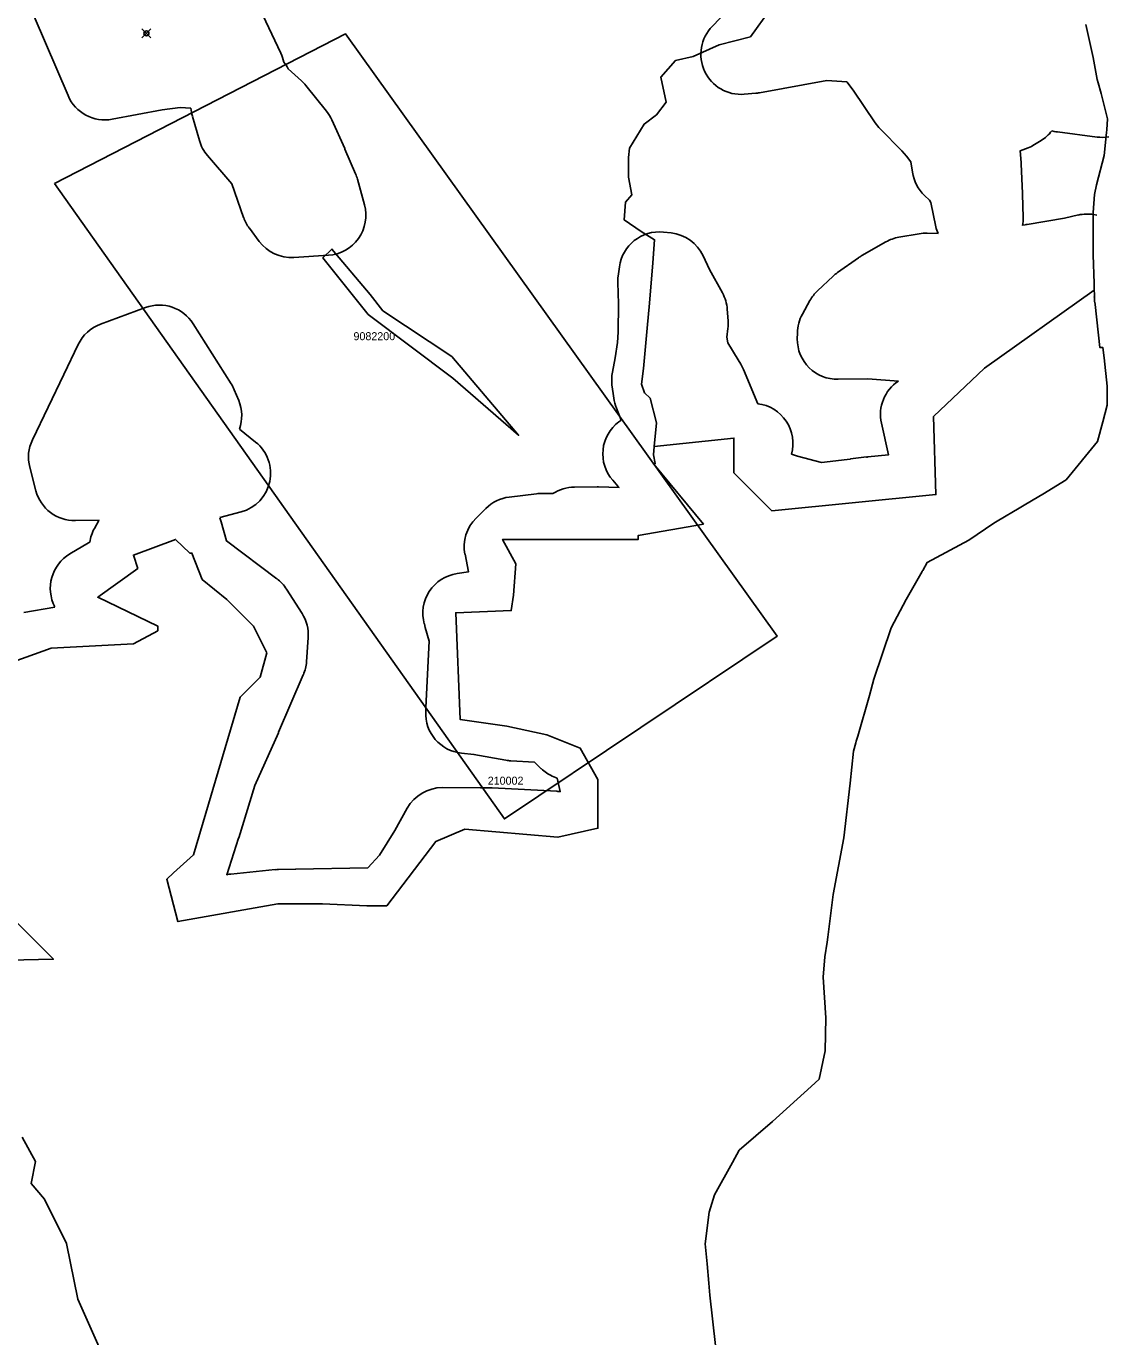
# Model space of a CAD drawing. Extents: x -546762 to -536351, y -1046851 to -1035695.
# Drawn here: x -541589 to -540237, y -1040804 to -1039166 of the extents above; entities that cross this region are included whole.
import ezdxf

# ---------------------------------------------------------------- set-up
doc = ezdxf.new("R2010")
doc.units = 0
for name, color, linetype in [('Vrstva 23', 7, 'Continuous'), ('Vrstva 24', 7, 'Continuous'), ('Vrstva 43', 7, 'Continuous'), ('Vrstva 46', 7, 'Continuous'), ('Vrstva 49', 7, 'Continuous')]:
    doc.layers.add(name, color=color, linetype=linetype)

msp = doc.modelspace()

# ---------------------------------------------------------------- linework, layer by layer
at = {"layer": 'Vrstva 23'}
for points in [[(-540687, -1039021.4), (-540674.7, -1039016.8), (-540651.8, -1039025.4), (-540649.4, -1039037.7), (-540668.5, -1039076.7), (-540699, -1039130.7), (-540722.5, -1039156.4), (-540732, -1039166)], [(-541271.1, -1039199.7), (-541316, -1039104.2)], [(-541579.2, -1039153.9), (-541536.9, -1039252.8)], [(-541245.2, -1039234.4), (-541262, -1039219.2)], [(-541214, -1039272.4), (-541239.9, -1039240.2)], [(-540673.2, -1039249.2), (-540588.9, -1039234), (-540564.1, -1039235.7), (-540556.2, -1039246), (-540528.6, -1039286.9)], [(-540692.2, -1039251), (-540677.9, -1039249.8)], [(-541481.7, -1039282.3), (-541419.5, -1039270.7), (-541397, -1039267.7), (-541383.5, -1039268.3)], [(-541381.6, -1039278.7), (-541372.8, -1039309)], [(-541191.3, -1039319), (-541207.4, -1039283.2)], [(-540522.6, -1039294.1), (-540495.3, -1039321.6), (-540489.4, -1039328.3), (-540484, -1039335.5), (-540482.1, -1039348.6)], [(-540308.1, -1039296.9), (-540304.9, -1039297.5)], [(-540329.7, -1039314), (-540321.5, -1039308.9)], [(-540301.1, -1039298.2), (-540251.5, -1039304.6)], [(-541362.8, -1039327.6), (-541332.3, -1039363.2), (-541317.5, -1039405.3)], [(-541177.7, -1039350.6), (-541191, -1039319.7)], [(-540346.4, -1039336.4), (-540347.6, -1039321.9), (-540337.7, -1039318)], [(-540344.6, -1039375.2), (-540346.3, -1039338.1)], [(-541166.6, -1039389.2), (-541175.4, -1039357.1)], [(-540466.9, -1039377.5), (-540460.8, -1039383.3), (-540459.3, -1039386.4), (-540452.8, -1039416.7)], [(-540343.8, -1039405.2), (-540344.6, -1039376.1)], [(-540274.8, -1039402), (-540292.2, -1039406), (-540338.9, -1039413.8)], [(-540251.8, -1039402.1), (-540255.4, -1039401.5)], [(-541310.4, -1039418.5), (-541298.2, -1039435)], [(-540783.6, -1039424.5), (-540793.2, -1039423.5)], [(-540473.8, -1039425.5), (-540498.9, -1039429.8)], [(-540450.1, -1039425.3), (-540463.8, -1039424.8)], [(-540341.1, -1039414.2), (-540344.5, -1039414.9)], [(-540515.2, -1039435.6), (-540545.4, -1039452.8)], [(-541254.8, -1039455.1), (-541211.6, -1039452.3)], [(-540719.5, -1039499.4), (-540735.7, -1039470.3), (-540743.7, -1039453.1)], [(-540549.6, -1039455.4), (-540575.7, -1039473.8)], [(-540848.2, -1039466.8), (-540849.6, -1039478.5)], [(-540850, -1039486.5), (-540849.1, -1039513.2), (-540849.5, -1039548.5), (-540850.4, -1039561.4), (-540853.5, -1039580.4), (-540856.9, -1039598.6)], [(-540581.1, -1039478.3), (-540600.7, -1039496.8)], [(-540610.1, -1039508.9), (-540619.5, -1039525.9)], [(-541440.1, -1039517.8), (-541496.4, -1039538.6)], [(-540712.3, -1039534.1), (-540713.4, -1039519.9)], [(-541333.1, -1039613), (-541380.6, -1039538)], [(-540699.9, -1039583), (-540712.9, -1039561.7), (-540713.8, -1039554.6), (-540712.5, -1039543.9)], [(-540625.8, -1039549.6), (-540625.9, -1039556.9)], [(-541524.2, -1039563.8), (-541542.2, -1039601.4), (-541542.2, -1039601.4), (-541581.4, -1039683)], [(-540696.6, -1039588.4), (-540699.9, -1039583.1)], [(-540675.4, -1039637.9), (-540693.1, -1039595.3)], [(-540575, -1039607.4), (-540538, -1039606.7), (-540499.5, -1039609.6)], [(-541323.7, -1039633.8), (-541329.2, -1039620.6)], [(-540857.4, -1039614.2), (-540856, -1039625.2)], [(-540856, -1039625.2), (-540855.2, -1039630.9)], [(-540851.9, -1039643.4), (-540845.9, -1039658.3)], [(-541302.6, -1039685.8), (-541322.8, -1039669.6)], [(-540846.3, -1039658.7), (-540848.9, -1039660.6)], [(-540520.9, -1039662.1), (-540512.2, -1039701.9), (-540537.9, -1039704.4)], [(-540559.8, -1039707.1), (-540563.5, -1039707.6), (-540595.5, -1039711.3), (-540625.8, -1039703.6), (-540633.3, -1039701)], [(-540539.3, -1039704.5), (-540559.4, -1039707)], [(-541584.6, -1039717.3), (-541576.9, -1039746.7)], [(-540856.5, -1039733.6), (-540850.1, -1039740.9)], [(-540951.6, -1039750.4), (-540985.8, -1039754.6)], [(-540931.2, -1039750.1), (-540945.1, -1039750)], [(-540875.8, -1039741.9), (-540904.3, -1039742.1)], [(-540849.6, -1039741.5), (-540848.6, -1039742.6), (-540874.1, -1039741.9)], [(-541347.3, -1039780.3), (-541320.7, -1039773.1)], [(-541014.9, -1039768.7), (-541027.2, -1039780.8)], [(-541527.6, -1039784), (-541498.2, -1039783.5)], [(-541498.5, -1039784), (-541503.9, -1039793.7)], [(-541276, -1039856.6), (-541338.8, -1039809.3), (-541345.6, -1039785.5)], [(-541511.3, -1039811.9), (-541534.5, -1039825.7)], [(-541041, -1039826.1), (-541036.7, -1039848.1), (-541050.9, -1039850.2)], [(-541244.6, -1039900), (-541263.9, -1039869.7)], [(-541553.3, -1039892), (-541591.9, -1039898.9)], [(-541091.8, -1039913.1), (-541090.6, -1039917.5), (-541085.9, -1039934.7), (-541089.9, -1040017.8)], [(-541239.1, -1039960.4), (-541237, -1039930.3)], [(-541273.8, -1040048.5), (-541243, -1039976.6)], [(-541089.9, -1040017.8), (-541090.1, -1040022.7)], [(-541323.7, -1040180.4), (-541303.5, -1040115.1), (-541274.1, -1040049.2)], [(-541045.2, -1040074.8), (-541029.9, -1040076.3), (-540989.9, -1040083.5)], [(-540983.7, -1040084.2), (-540954.3, -1040085.8), (-540945.7, -1040094.1)], [(-540932.1, -1040103.3), (-540925.9, -1040106.1), (-540922, -1040122.7), (-540923.6, -1040122.6)], [(-541009.5, -1040117.9), (-541021.7, -1040117.9), (-541069.3, -1040117.8)], [(-540926.3, -1040122.4), (-541007, -1040118)], [(-541113.1, -1040143.4), (-541128.8, -1040171.5), (-541147.8, -1040202.2), (-541162.3, -1040218), (-541252.6, -1040219.7)], [(-541337.6, -1040226.4), (-541338.7, -1040226.6), (-541323.9, -1040181)], [(-541278.2, -1040220.3), (-541333.7, -1040225.8)], [(-541252.6, -1040219.7), (-541274.2, -1040220.1)]]:
    msp.add_lwpolyline(points, dxfattribs=at)
for centre, start, end in [((-540696.4, -1039201.2), 135.2787, 274.7968), ((-541316.4, -1039221), 11.6578, 25.1714), ((-541306.5, -1039242.1), 27.3262, 38.687), ((-541278.9, -1039271.4), 38.7334, 47.7618), ((-541490.9, -1039233.1), 203.1566, 280.5586), ((-540682.1, -1039200), 274.7968, 280.2491), ((-541333.6, -1039264.7), 184.1005, 196.1993), ((-541253, -1039303.7), 24.2144, 38.7334), ((-540487.1, -1039258.9), 214.0406, 224.7993), ((-540347.7, -1039266.4), 301.6423, 322.4121), ((-540294.7, -1039248.6), 258.2417, 262.6546), ((-541324.8, -1039295.1), 196.1993, 220.5926), ((-540355.9, -1039271.5), 291.4062, 301.6423), ((-540245.1, -1039255), 262.6546, 279.5263), ((-541236.9, -1039339.5), 23.2769, 24.2144), ((-540396.3, -1039340.4), 2.6117, 4.5691), ((-541223.6, -1039370.3), 15.3684, 23.2769), ((-540432.6, -1039341.2), 188.5527, 226.6352), ((-540394.6, -1039377.5), 1.5561, 2.6117), ((-541214.8, -1039402.4), 273.6531, 15.3684), ((-541270.3, -1039388.7), 199.3971, 216.6026), ((-540393.8, -1039406.6), 350.4057, 1.5561), ((-540263.7, -1039450.8), 80.4998, 102.7951), ((-540798.6, -1039473.2), 83.7978, 172.7477), ((-540789, -1039474.2), 24.9468, 83.7978), ((-540465.4, -1039474.8), 88.2017, 99.7174), ((-540403.9, -1039406.2), 192.1517, 202.4009), ((-540330.7, -1039463.1), 99.445, 101.9338), ((-541258, -1039405.2), 216.6026, 273.6531), ((-540490.5, -1039479.1), 99.7174, 119.5569), ((-540520.8, -1039496.3), 119.5569, 125.2703), ((-540546.8, -1039514.7), 125.2703, 133.3763), ((-540800.1, -1039484.8), 172.7477, 181.9352), ((-540763.2, -1039523.7), 4.2841, 29.0498), ((-540566.4, -1039533.2), 133.3763, 150.9711), ((-541422.8, -1039564.7), 32.3202, 110.2362), ((-540575.8, -1039550.2), 150.9711, 179.366), ((-541479.1, -1039585.5), 110.2362, 154.352), ((-540762.2, -1039537.8), 353.0657, 4.2841), ((-540575.9, -1039557.4), 179.366, 271.0512), ((-540742.5, -1039609.1), 31.373, 31.4212), ((-540739.3, -1039614.4), 22.5577, 31.373), ((-540807.8, -1039607.9), 169.294, 187.2663), ((-541375.4, -1039639.7), 22.45, 32.3202), ((-540806.4, -1039618.9), 187.2663, 187.3108), ((-540472.1, -1039651.4), 123.2647, 192.4075), ((-541369.9, -1039652.9), 340.4575, 22.45), ((-540805.6, -1039624.5), 187.3108, 202.159), ((-540681.4, -1039687.5), 344.3403, 83.0992), ((-540816.4, -1039698.7), 126.1246, 126.7976), ((-540818.9, -1039700.6), 126.7976, 221.314), ((-541536.3, -1039704.6), 154.3549, 194.6946), ((-541333.8, -1039724.9), 285.1759, 51.3277), ((-540553.2, -1039756.6), 97.1004, 97.5856), ((-540533.1, -1039754.2), 95.5519, 97.1004), ((-541528.6, -1039734), 194.6946, 271.0698), ((-540979.7, -1039804.2), 97.0508, 134.7185), ((-540945.5, -1039800), 89.4765, 97.0508), ((-540904, -1039792.1), 90.4009, 122.9834), ((-540875.4, -1039791.9), 88.4792, 90.4009), ((-540812.6, -1039707.9), 221.314, 222.2515), ((-541454.8, -1039808.4), 150.1205, 150.7815), ((-541393.7, -1039799.2), 15.8145, 22.1185), ((-540992, -1039816.4), 134.7185, 191.2035), ((-541460.3, -1039818.1), 150.7815, 171.8664), ((-541485.8, -1039854.9), 118.7077, 120.6621), ((-541509, -1039868.7), 120.6621, 207.698), ((-541043.7, -1039899.7), 98.3818, 195.557), ((-541306.1, -1039896.5), 32.3928, 53.0281), ((-541286.8, -1039926.8), 355.9822, 32.3928), ((-541288.9, -1039956.9), 336.7947, 355.9822), ((-541039.9, -1040020.2), 177.2255, 177.2737), ((-541040.2, -1040025), 177.2737, 264.2072), ((-541319.8, -1040028.8), 335.9562, 336.7947), ((-540981.1, -1040034.3), 259.8374, 266.9551), ((-540911.2, -1040057.9), 226.3449, 245.2107), ((-541069.4, -1040167.8), 89.8555, 150.8568), ((-541009.7, -1040167.9), 86.9216, 89.8589), ((-540929, -1040172.3), 83.7774, 86.9216), ((-541371.5, -1040165.6), 342.0457, 342.7969), ((-541328.8, -1040275.6), 95.6482, 100.1404), ((-541273.2, -1040270.1), 91.0874, 95.6482), ((-541251.6, -1040269.7), 91.0752, 91.0874)]:
    msp.add_arc(centre, 50, start, end, dxfattribs=at)
at = {"layer": 'Vrstva 24'}
for points in [[(-540659.7, -1039145.3), (-540684.5, -1039179.1), (-540723.5, -1039189.5), (-540756.1, -1039203.8), (-540778.2, -1039209), (-540796.4, -1039229.9), (-540789.9, -1039261.1), (-540801.6, -1039276.7), (-540817.2, -1039288.4), (-540835.4, -1039318.4), (-540836.8, -1039330.1), (-540836.8, -1039354.8), (-540832.8, -1039376.9), (-540840.7, -1039386), (-540842, -1039408.2), (-540821.1, -1039422.5), (-540804.2, -1039432.9), (-540806.5, -1039461.7), (-540810.7, -1039512.3), (-540813.3, -1039543.5), (-540818.2, -1039593.8), (-540820.6, -1039613.3), (-540816.7, -1039624.1), (-540809.9, -1039630.9), (-540801.6, -1039661.6), (-540804.7, -1039691.3), (-540705, -1039680.8), (-540705, -1039724.5), (-540657.9, -1039771.6), (-540452.7, -1039751.4), (-540456, -1039653.9), (-540392.1, -1039593.3), (-540254.9, -1039496)], [(-540254.9, -1039496), (-540255.2, -1039487.7), (-540256.3, -1039452), (-540256.4, -1039398.8), (-540254.6, -1039376.5), (-540252.2, -1039364.5), (-540242.8, -1039327.7), (-540239.5, -1039298.8), (-540239.3, -1039295.7), (-540238.5, -1039282), (-540245.1, -1039255), (-540246.3, -1039250.1), (-540249.9, -1039237), (-540251.2, -1039232.6), (-540256.2, -1039205.1), (-540265.4, -1039163.9)], [(-540254.9, -1039496), (-540392.1, -1039593.3), (-540456, -1039653.9), (-540452.7, -1039751.4), (-540657.9, -1039771.6), (-540705, -1039724.5), (-540705, -1039680.8), (-540804.7, -1039691.3), (-540805.5, -1039701.6), (-540803.3, -1039712.8), (-540805.2, -1039713.3), (-540805.3, -1039713.3), (-540743.2, -1039788.3), (-540824.6, -1039802.5), (-540824.6, -1039807.6), (-540994, -1039807.6), (-540977.7, -1039838.1), (-540980.4, -1039877), (-540983.2, -1039896.4), (-541052.6, -1039899.2), (-541047.1, -1040032.5), (-540988.8, -1040040.8), (-540938.8, -1040051.9), (-540897.1, -1040068.6), (-540874.9, -1040107.5), (-540874.9, -1040168.5), (-540924.9, -1040179.7), (-541041.1, -1040169.8), (-541077.6, -1040185.2), (-541138.7, -1040265.7), (-541163.7, -1040265.7), (-541219.2, -1040263), (-541274.8, -1040263), (-541399.7, -1040285.2), (-541413.6, -1040232.4), (-541405.3, -1040224.1), (-541380.3, -1040201.9), (-541322, -1040004.7), (-541297, -1039979.7), (-541288.7, -1039949.2), (-541305.3, -1039915.9), (-541338.6, -1039882.5), (-541369.2, -1039857.5), (-541382.2, -1039824.5), (-541384.8, -1039824.5), (-541402.5, -1039807.6), (-541455.3, -1039827), (-541449.7, -1039843.7), (-541499.7, -1039879.8), (-541424.6, -1039916), (-541424.6, -1039921.6), (-541455.3, -1039938.1), (-541558, -1039943.6), (-541705.2, -1039996.4)], [(-540728.2, -1040815.2), (-540735.1, -1040752.1), (-540736.5, -1040737.2), (-540738.7, -1040712.9), (-540741.2, -1040688.2), (-540736.1, -1040648.6), (-540729.2, -1040626.7), (-540707, -1040586.2), (-540698.7, -1040571.1), (-540656.7, -1040535.1), (-540608.8, -1040491.4), (-540598.8, -1040482.3), (-540591, -1040446.8), (-540590.4, -1040405.4), (-540593.5, -1040354.7), (-540591.5, -1040329.4), (-540588.7, -1040311), (-540587.9, -1040304.9), (-540581.1, -1040251.2), (-540567.6, -1040180.7), (-540559.8, -1040112.4), (-540555.8, -1040072.3), (-540552.8, -1040061.7), (-540552.2, -1040059.8), (-540550.7, -1040054.7), (-540550.3, -1040053.3), (-540535.8, -1040002.7), (-540530.4, -1039982.1), (-540508.7, -1039918.1), (-540490.1, -1039882.7), (-540471.7, -1039850.5), (-540471.4, -1039850), (-540469.9, -1039847.4), (-540469.3, -1039846.4), (-540463.5, -1039836.2), (-540411.8, -1039808.5), (-540380.6, -1039787.4), (-540363.1, -1039776.9), (-540360, -1039775.1), (-540331.5, -1039758.2), (-540319.1, -1039751.1), (-540290.2, -1039733.2), (-540250.8, -1039685.1), (-540244.3, -1039660.5), (-540238.8, -1039639.6), (-540238.7, -1039616.1), (-540242.8, -1039580.5), (-540244.1, -1039567.8), (-540248.1, -1039567.6), (-540253.8, -1039513.8), (-540253.9, -1039513.6), (-540254.6, -1039509.6), (-540254.6, -1039506.2), (-540254.8, -1039505), (-540254.9, -1039505.1), (-540254.7, -1039503.9), (-540254.7, -1039501.1), (-540254.9, -1039496)], [(-541641.3, -1040246.3), (-541555.2, -1040332.4), (-541816.2, -1040337.9)], [(-541594.1, -1040554.5), (-541577.4, -1040585.1), (-541583, -1040612.8), (-541566.3, -1040632.3), (-541538.6, -1040687.8), (-541524.7, -1040757.2), (-541491.4, -1040832.2)]]:
    msp.add_lwpolyline(points, dxfattribs=at)
at = {"layer": 'Vrstva 43'}
msp.add_lwpolyline([(-541159.3, -1039501.5), (-541207.2, -1039444.6), (-541218.8, -1039455.6), (-541162.1, -1039526.2), (-541056.2, -1039606.1), (-540974, -1039677.3), (-541057.4, -1039578.9), (-541143.6, -1039521.6)], close=True, dxfattribs=at)
at = {"layer": 'Vrstva 46'}
msp.add_lwpolyline([(-541553.6, -1039362.8), (-540991.8, -1040156.9), (-540650.9, -1039928.4), (-541190.3, -1039175.5)], close=True, dxfattribs=at)
at = {"layer": 'Vrstva 49'}
for p, q in [((-541444.5, -1039180.5), (-541433.5, -1039169.5)), ((-541444.5, -1039169.5), (-541433.5, -1039180.5))]:
    msp.add_line(p, q, dxfattribs=at)
msp.add_circle((-541439, -1039175), 3.08, dxfattribs=at)

# ---------------------------------------------------------------- texts
at = {"layer": 'Vrstva 43'}
msp.add_text('9082200', height=10, dxfattribs=at).set_placement((-541180.3, -1039558.5))
at = {"layer": 'Vrstva 46'}
msp.add_text('210002', height=10, dxfattribs=at).set_placement((-541012.6, -1040114.1))

doc.saveas('drawing.dxf')
